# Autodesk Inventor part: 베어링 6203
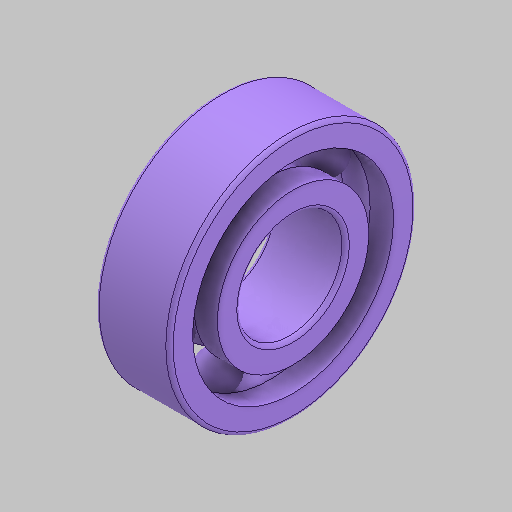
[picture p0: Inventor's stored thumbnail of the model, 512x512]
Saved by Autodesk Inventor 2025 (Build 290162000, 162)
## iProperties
Created: 2024-08
Part Number: 베어링 6203
Material: 스테인리스강
Description: 깊은 그루브 볼 베어링
Document SubType Name: Modeling
Designer: 현기
Density: 8.08 g/cm^3
Appearance: 기본값
Author: jhkim
Sending System: Autodesk Inventor 2025
Preprocessor: ST-DEVELOPER v20
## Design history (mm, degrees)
feature "Solid1"
feature "Solid1:1"
feature "Solid1:2"
feature "Solid1:3"
feature "Solid1:4"
feature "Solid1:5"
feature "Solid1:6"
feature "Solid1:7"
feature "Solid1:8"
node "솔리드1"
node "솔리드2"
node "솔리드3"
node "솔리드4"
node "솔리드5"
node "솔리드6"
node "솔리드7"
node "솔리드8"
node "솔리드9"
